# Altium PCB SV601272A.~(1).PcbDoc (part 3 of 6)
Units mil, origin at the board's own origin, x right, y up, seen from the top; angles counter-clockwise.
Board outline 8300 x 9520 mil, 8 copper layers (Top Layer, Signal Layer 1, Signal Layer 2, Signal Layer 3, Signal Layer 4, Signal Layer 5, Signal Layer 6, Bottom Layer), stack 59.2 mil thick; 551 components, 303 nets, 1611 pads, 1923 vias.
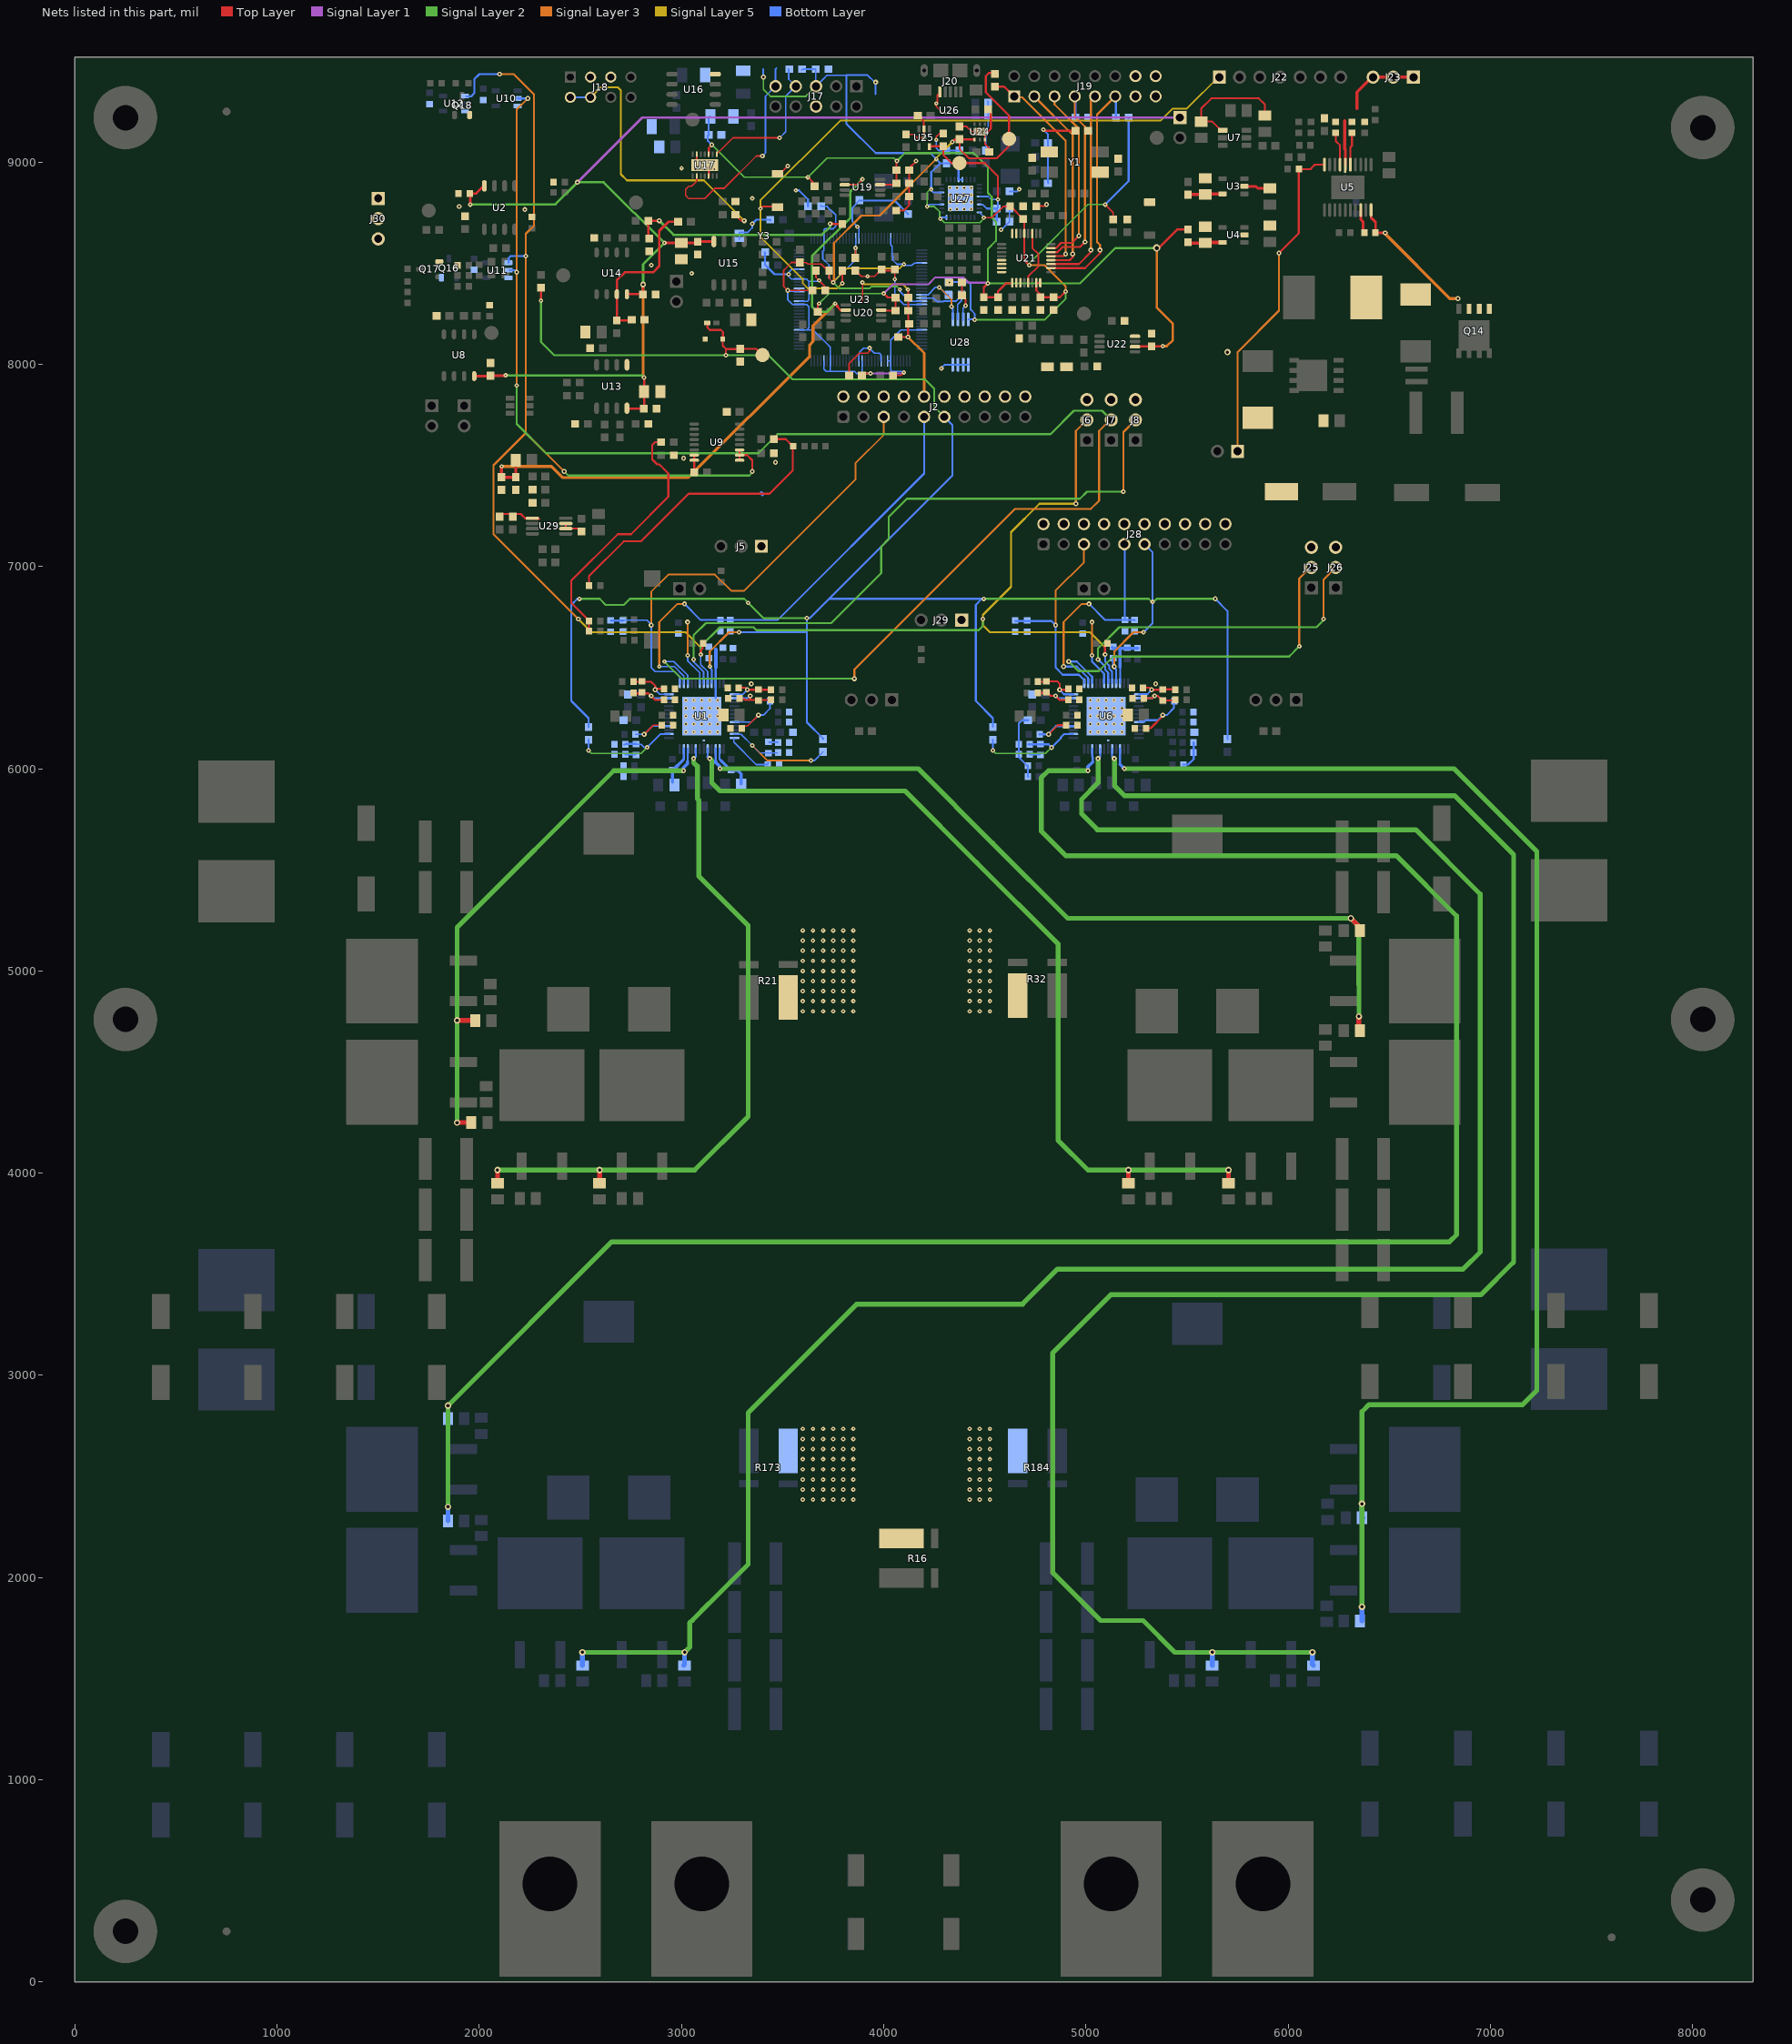
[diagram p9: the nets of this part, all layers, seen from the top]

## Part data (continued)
R142: "RES, 0, 5%, 0.1 W, 0603", Manufacturer=Vishay-Dale, Power_W=0.1, Supplier Part Number 1=541-0.0GCT-ND, TempCo="200 ppm/C", Tolerance_%=5, Value1=5%, Value2=0.1W, Value_Code=0000, ValueDisplayed=0
R143: "RES, 4.87 k, 1%, 0.1 W, 0603", Manufacturer=Vishay-Dale, Power_W=0.1, Supplier Part Number 1=541-4.87KHCT-ND, TempCo="100 ppm/C", Tolerance_%=1, Value1=1%, Value2=0.1W, Value_Code=4k87, ValueDisplayed=4.87k
R145: "RES, 2.00 k, 1%, 0.1 W, 0603", Manufacturer=Vishay-Dale, Power_W=0.1, Supplier Part Number 1=541-2.00KHCT-ND, TempCo="100 ppm/C", Tolerance_%=1, Value1=1%, Value2=0.1W, Value_Code=2k00, ValueDisplayed=2.00k
R146: "RES, 51, 5%, 0.1 W, 0603", Manufacturer=Vishay-Dale, Power_W=0.1, Supplier Part Number 1=541-51GCT-ND, TempCo="200 ppm/C", Tolerance_%=5, Value1=5%, Value2=0.1W, Value_Code=51R0, ValueDisplayed=51
R149: "RES, 1.00 k, 1%, 0.1 W, 0603", Manufacturer=Vishay-Dale, Power_W=0.1, Supplier Part Number 1=541-1.00KHCT-ND, TempCo="100 ppm/C", Tolerance_%=1, Value1=1%, Value2=0.1W, Value_Code=1k00, ValueDisplayed=1.00k
R153: "RES, 8.06 k, 1%, 0.1 W, 0603", Manufacturer=Vishay-Dale, Power_W=0.1, Supplier Part Number 1=541-8.06KHCT-ND, TempCo="100 ppm/C", Tolerance_%=1, Value1=1%, Value2=0.1W, Value_Code=8k06, ValueDisplayed=8.06k
R162: library part CMP-0025080-3, "RES, 2.00 k, 0.5%, 0.1 W, 0603", Manufacturer="Yageo America", Power_W=100mW, TempCo="50 ppm/C", Tolerance_%=0.5%, Value2=0.1W, Value_Code=2k00, ValueDisplayed=2.00k
R200: library part CMP-0023560-3, "RES, 4.87 k, 0.1%, 0.1 W, 0603", Manufacturer="Susumu Co Ltd", Power_W=100mW, Supplier Part Number 1=RG16P4.87KBCT-ND, TempCo="25 ppm/C", Tolerance_%=0.1%, Value2=0.1W, Value_Code=4k87, ValueDisplayed=4.87k
R201: "RES, 4.70, 0.5%, 0.1 W, 0603", Manufacturer="Yageo America", Power_W=0.1, TempCo="50 ppm/C", Tolerance_%=0.5, Value1=0.5%, Value2=0.1W, Value_Code=4R70, ValueDisplayed=4.70
S1: library part CMP-0002143-3, "Switch, Tactile, SPST-NO, 0.05A, 12V, SMT", CurrentRating_mA=50A, Manufacturer=E-Switch, PartNumber=TL1015AF160QG, Supplier Part Number 1=EG4344CT-ND
S2: "Switch, Tactile, SPST-NO, 0.05A, 12V, SMT", CurrentRating_mA=50, Manufacturer=E-Switch, Supplier Part Number 1=EG4344CT-ND
S3: "Switch"
T1 T2 T3 T4: "Terminal 70A Lug", Manufacturer=Panduit, Supplier Part Number 1=CXS70-14-C-ND
U1 U6: "Dual Channel 48V-12V Bidirectional Current Controller, PHP0048D", Alternate Manufacturer="Texas Instruments", Alternate PartNumber=LM5170QPHPTQ1
U2: library part LM6142AIM, "17MHz Rail-to-Rail Input and Output Op Amp, D0008A", Alternate Manufacturer="Texas Instruments"
U3 U4: "150-mA, 30-V, 1-uA IQ Voltage Regulators with Enable, DBV0005A", Alternate Manufacturer="Texas Instruments", Alternate PartNumber=TPS70950DBVT
U5: "Wide Voltage Range Buck-Boost Controller, 20-pin TSSOP-EP, Pb-Free", Manufacturer="Texas Instruments", PackageTopMarking=NSUZXYTT*LM5118*MH, PowerWise=Y, Supplier Part Number 1=LM5118MH-ND
U7: library part CMP-0072146-1, "Switched Capacitor Voltage Converter, 6-pin SOT-23", Manufacturer="Texas Instruments", PackageTopMarking=S03A*XTT, PowerWise=N
U8 U14: library part CMP-0041267-2, "Low-Noise, High-Precision, JFET-Input Operational Amplifier, 8 to 36 V, -40 to 125 degC, 8-pin SOIC (D8), Green (RoHS & no Sb/Br)", Manufacturer="Texas Instruments"
U9: library part CMP-0076549-1, "TRIPLE 2-CHANNEL ANALOG MULTIPLEXER/DEMULTIPLEXER, PW0016A (TSSOP-16)", Alternate Manufacturer="Texas Instruments"
U10: "Single Inverter Gate, DBV0005A", Alternate Manufacturer="Texas Instruments"
U11: "Single Power Supply 2-Input Positive NAND Gate CMOS Logic Level Shifter, DBV0005A", Alternate Manufacturer="Texas Instruments"
U12: "Single Power Supply 2-Input Positive OR Gate CMOS Logic Level Shifter, DBV0005A", Alternate Manufacturer="Texas Instruments"
U13: library part CMP-0079943-1, "50-uV Offset, 7-nV/vHz Noise, Low-Power, Precision Instrumentation Amplifier, D0008A (SOIC-8)", Alternate Manufacturer="Texas Instruments", Alternate PartNumber=INA828IDR
U15: library part CMP-0079847-1, "36-V Precision, Rail-to-Rail Output, Operational Amplifier, D0008A (SOIC-8)", Alternate Manufacturer="Texas Instruments"
U16: library part CMP-0032617-1, "Low Noise, Very Low Drift, Precision Voltage Reference, -40 to 125 degC, 8-pin SOIC (D), Green (RoHS & no Sb/Br)", Manufacturer="Texas Instruments", PartNumber=REF5050AID, Rating=Catalog, Temp Coeff(Max)(ppm/ degree C)=3
U17: library part CMP-0013342-2, "QUAD 16-BIT, 1LSB INL, BUFFERED, VOLTAGE-OUTPUT DIGITAL-to-ANALOG CONVERTERS, DMD0014A (VSON-14)", Alternate Manufacturer="Texas Instruments", PartNumber=DAC80004IDMD
U19 U20: library part CMP-0074888-1, "Low-Power, High Supply Range, 60-MHz, Fully Differential Amplifier, DGK0008A (VSSOP-8)", Alternate Manufacturer="Texas Instruments", Alternate PartNumber=THS4561IDGKT
U21: library part CMP-0075938-2, "24-Bit, 128kSPS, 4-Ch, Simultaneous Sampling, Delta-Sigma ADC, PBS0032A (TQFP-32)", Alternate Manufacturer="Texas Instruments", Alternate PartNumber=ADS131A04IPBS
U22: library part CMP-0032584-1, "Low Noise, Very Low Drift, Precision Voltage Reference, -40 to 125 degC, 8-pin MSOP(DGK), Green (RoHS & no Sb/Br)", Manufacturer="Texas Instruments", PartNumber=REF5025IDGKR, Rating=Military, Temp Coeff(Max)(ppm/ degree C)=3
U23: library part CMP-0029864-2, "Tiva C Series Microcontroller, 1024 KB Flash, 256 KB SRAM, 12 Bit, 20 Channels, -40 to 85 degC, 128-Pin TQFP (PDT), Green (RoHS & no Sb/Br), Tape and Reel", Manufacturer="Texas Instruments", Temperature Range="-40 to 85 degC"
U24: "1-A Low-Dropout Regulator With Reverse Current Protection, DRV0006A", Alternate Manufacturer="Texas Instruments", Alternate PartNumber=TPS73733DRVT
U25: "Single Output High PSRR LDO, 150 mA, Fixed 1.8 V Output, 2.5 to 6.5 V Input, with Low IQ, 5-pin SC70 (DCK), -40 to 85 degC, Green (RoHS & no Sb/Br)", Alternate Manufacturer="Texas Instruments", Alternate PartNumber=Equivalent, Supplier Part Number 1=296-19646-2-ND
U26: library part CMP-0043122-2, "USB ESD Solution with Power Clamp, 4 Channels, -40 to +85 degC, 6-pin SON (DRY), Green (RoHS & no Sb/Br)", Breakdown Voltage(Min)(V)=6, IO Capacitance(Typ)(pF)=0.8, IO Leakage Current(nA)=10, Manufacturer="Texas Instruments"
U27: "Highly Integrated Full Featured Hi-Speed USB 2.0 ULPI Transceiver, QFN-32", Manufacturer=Microchip, Supplier Part Number 1=USB3320C-EZK-ND
U28: "256K I2C™ CMOS Serial EEPROM, TSSOP-8", Manufacturer=Microchip, Supplier Part Number 1=24AA256-I/ST-ND
U29: "Low Noise Negative Bias Generator, 8-pin Mini SOIC, Pb-Free", Manufacturer="Texas Instruments", PackageTopMarking=ZXTT*F26A, PowerWise=N, Supplier Part Number 1=LM7705MM-ND
Y1: library part CMP-0004606-3, "Crystal, 16.384 MHz, 20 pF, SMD", Frequency_Fixed=16.384MHz, Frequency Stability=+/-50ppm, Manufacturer="CTS Electrocomponents", PartNumber=407F35E016M3840, Supplier Part Number 1=CTX682CT-ND
Y2: "Crystal, 25 MHz, 18 pF, SMD", Frequency="25 MHz", Frequency Stability=±30ppm, Manufacturer="Abracon Corportation", Supplier Part Number 1=535-10645-1-ND
Y3: "CRYSTAL, 32.768KHZ, 7PF, SMD", Frequency=32.768KHZ, Frequency Stability=±20ppm, Manufacturer="Seiko Instruments", Supplier Part Number 1=728-1065-1-ND
Y4: "Crystal, 24 MHz, 18 pF, SMD", Frequency="24 MHz", Frequency Stability=±30ppm, Manufacturer="Abracon Corportation", Supplier Part Number 1=535-10643-1-ND
ZZ1: library part AssemblyNoteLabel, Alternate Manufacturer=-
ZZ2 ZZ3 ZZ4: library part AssemblyNote, Alternate Manufacturer=-

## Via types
v1: diameter 32, hole 16, Top Layer to Bottom Layer, tented both sides, 622 vias
v2: diameter 24, hole 8, Top Layer to Bottom Layer, 380 vias
v3: diameter 22, hole 8, Top Layer to Bottom Layer, tented both sides, 346 vias
v4: diameter 32, hole 16, Top Layer to Bottom Layer, 237 vias
v5: diameter 24, hole 10, Top Layer to Bottom Layer, tented both sides, 153 vias
v6: diameter 19.68, hole 7.87, Top Layer to Bottom Layer, 70 vias
v7: diameter 24, hole 10, Top Layer to Bottom Layer, 47 vias
v8: diameter 28, hole 8, Top Layer to Bottom Layer, tented top, 24 vias
v9: diameter 22, hole 8, Top Layer to Bottom Layer, 19 vias
v10: diameter 19.68, hole 8, Top Layer to Bottom Layer, 16 vias
v11: diameter 50, hole 28, Top Layer to Bottom Layer, 4 vias
v12: diameter 36, hole 20, Top Layer to Bottom Layer, 2 vias
v13: diameter 26, hole 12, Top Layer to Bottom Layer, 1 vias
v14: diameter 28, hole 12, Top Layer to Bottom Layer, tented both sides, 1 vias
v15: diameter 24, hole 10, Top Layer to Bottom Layer, tented top, 1 vias

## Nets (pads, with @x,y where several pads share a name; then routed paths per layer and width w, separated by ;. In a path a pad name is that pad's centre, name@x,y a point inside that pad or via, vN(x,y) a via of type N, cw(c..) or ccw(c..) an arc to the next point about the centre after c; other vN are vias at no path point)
1.8V: C177.2 C178.2 C183.1 U25.5 U27.28 U27.30 V1.8.1 | length 842.3
  Top Layer w10: U25.5@4225,9080 4226.5,9078.5 C183.1@4295,9078.5 4295,9035 4335,8995 V1.8.1@4375,8995 4500,8995 4565,8930 v3(4565,8815)
  Bottom Layer w6: U27.30@4475,8790 4490,8790 4510,8770 4511.24,8770
  Bottom Layer w8: U27.28@4473.31,8829.84 4517.51,8829.84 4532.35,8815 v3@4560,8815 ; C177.2@4560,8770 4565,8775 v3(4565,8815)
  Bottom Layer w10: 4511.24,8770 C177.2@4558.5,8770 ; C178.2@4555,8705 4558.5,8708.5 C177.2@4558.5,8770 ; C177.2@4560,8770 C177.2@4558.5,8770
-0.2V: C228.1 C229.1 L8.1 U19.6 U20.6 | length 3366.9
  Top Layer w9: U19.6@3807.4,8887.8 3867.8,8887.8 v3(3895,8915)
  Top Layer w12: v3(3760,8300) 3771.95,8288.05 3771.95,8283.97 ; 3770,8285 3787.2,8267.8 U20.6@3812.4,8267.8 U20.6@3809.54,8270.65
  Top Layer w15: C229.1@2105,7445 2108.5,7441.5 C229.1@2110,7441.5 ; v3(2110,7495) C229.1@2110,7441.5 ; C228.1@2180,7441.5 C229.1@2110,7441.5 ; C228.1@2180,7445 L8.1@2180,7525
  Signal Layer 2 w12: v3(3760,8300) 3720,8260 3670,8260 3645,8285 3645,8535 3835,8725 3835,8855 v3(3895,8915)
  Signal Layer 3 w15: v3(2110,7495) 2356.29,7495 2411.29,7440 3035,7440 3633.63,8038.63 3633.63,8096.37 3650,8112.75 3650,8190 v3(3760,8300)
-5V: C97.1 C108.1 C109.1 C112.1 C119.1 C120.1 C189.1 J16.1 U2.4 U8.4 U13.4 U14.4 U15.4 | length 6559.2
  Top Layer w12: v3(1955,8790) 1955,8845 1985,8845 U2.4@2025,8885 ; U8.4@1975,7941.65 2053.35,7941.65 C97.1@2055,7940 ; C97.1@2055,7943.5 v9@2131.5,7943.5 ; U13.4@2730,7782.72 2732.72,7780 C108.1@2813.5,7780 2815,7780 v9(2815,7935) ; U14.4@2730,8346.65 2803.35,8346.65 C112.1@2805,8345 ; C112.1@2808.5,8345 v14@2808.5,8393.5 ; v9(2915,8600) C120.1@3000,8600 3080,8600 3087.28,8607.28 U15.4@3160,8607.28
  Signal Layer 1 w12: v5(2485,8900) 2805,9220 J16.1@5465,9220
  Signal Layer 2 w12: v3(1955,8790) 1955.87,8790.87 2375.87,8790.87 v5(2485,8900) 2615,8900 v9(2915,8600) 2810,8495 v14(2810,8395) ; v9(2130,7945) 2805,7945 v9(2815,7935)
  Signal Layer 3 w12: v14(2810,8395) 2810,7935 v9@2815,7930
ADC_SPI_CS: J19.5 U21.23 | length 902.8
  Top Layer w10: U21.23@4827.05,8574.21 4827.95,8575.12 4852.54,8575.12 4877.42,8600 4930,8600 v7(4965,8635)
  Signal Layer 3 w10: J19.5@4845,9325 4845,9285 4965,9165 v7(4965,8635)
ADC_SPI_DONE: J19.11 R123.1 U21.18 | length 1198.6
  Top Layer w10: U21.18@4827.05,8475.79 4995.79,8475.79 5070,8550 v7(5070,8565)
  Signal Layer 3 w10: v7(5070,8565) 5070,8590 5055,8605 5055,9235 J19.11@5145,9325
  Bottom Layer w10: J19.11@5145,9325 5148.5,9321.5 R123.1@5148.5,9220
ADC_SPI_DRDY: J19.9 U21.19 | length 1000.9
  Top Layer w10: U21.19@4827.05,8495.47 4965.47,8495.47 5025,8555 v7(5025,8565)
  Signal Layer 3 w10: v7(5025,8565) 5025,8585 5025,9305 J19.9@5045,9325
ADC_SPI_MISO: J19.1 R122.1 U21.21 | length 1098.4
  Top Layer w10: R122.1@4550,9373.5 4596.5,9373.5 J19.1@4645,9325 J19.1@4646.5,9323.5 ; U21.21@4827.05,8534.84 4889.84,8534.84 v7(4900,8545)
  Signal Layer 3 w10: J19.1@4645,9320 4685,9320 4900,9105 v7(4900,8545)
ADC_SPI_MOSI: J19.3 U21.20 | length 987.8
  Top Layer w10: U21.20@4827.05,8515.16 4920.16,8515.16 4935,8530 v7(4935,8545)
  Signal Layer 3 w10: J19.3@4745,9325 4935,9135 v7(4935,8545)
ADC_SPI_SCLK: J19.7 R138.2 U21.22 | length 1043.1
  Top Layer w10: U21.22@4827.05,8554.53 4859.53,8554.53 4885,8580 4970,8580 v7(4995,8605)
  Signal Layer 3 w10: J19.7@4945,9330 J19.7@4945,9325 4945,9225 4995,9175 v7(4995,8605)
  Bottom Layer w10: J19.7@4940,9325 4948.5,9316.5 R138.2@4948.5,9220
AGND: C1.2 C2.1 C3.1 C5.2 C6.2 C8.2 C9.1 C11.2 C13.2 C14.2 C16.2 C17.2 C19.1 C31.2 C33.2 C34.2 C35.2 C36.2 C37.2 C44.2 C45.2 C72.2 C73.2 C74.2 C75.2 C76.2 C78.2 C82.2 C83.2 C84.2 C90.2 C91.1 C93.2 C94.1 C96.2 C97.2 C98.2 C99.1 C100.2 C104.2 C105.2 C106.2 C107.2 C108.2 C109.2 C110.2 C111.2 C112.2 C113.1 C116.2 C117.2 C118.1 C119.2 C120.2 C121.1 C122.2 C123.2 C124.2 C125.2 C126.2 C127.2 C128.2 C131.2 C132.2 C133.2 C134.2 C135.2 C136.2 C137.2 C138.2 C139.2 C140.2 C141.2 C145.1 C146.1 C149.1 C152.2 C153.2 C155.2 C156.2 C157.2 C158.2 C159.2 C160.2 C161.2 C189.2 C190.2 C191.2 C194.2 C196.2 C197.2 C199.2 C200.2 C202.2 C203.2 C204.2 C205.2 C218.2 C223.2 C224.2 C225.2 C226.2 C227.2 C228.2 C229.2 D5.2 J2.2 J2.4 J2.6 J2.8 J2.10 J2.12 J2.14 J2.16 J2.18 J2.20 J5.1 J6.3 J7.3 J8.3 J17.6 J18.3 J18.5 J19.13 J19.14 J19.15 J19.16 J23.1 J23.2 J23.3 J25.3 J26.3 J28.2 J28.4 J28.6 J28.8 J28.10 J28.12 J28.14 J28.16 J28.18 J28.20 J29.1 J30.1 J30.2 J30.3 NT1.1 NT2.1 NT3.1 Q16.2 Q17.2 Q18.2 R2.2 R3.2 R6.1 R7.2 R9.2 R11.1 R13.1 R15.1 R17.1 R18.1 R19.1 R20.1 R23.2 R46.1 R49.1 R67.1 R78.1 R86.2 R87.1 R89.2 R92.1 R112.1 R126.1 R138.1 R147.2 R148.1 R156.1 R158.1 R167.1 R169.1 R170.1 R171.1 R172.1 S1.2 U1.42 U1.46 U1.49 U3.2 U4.2 U5.6 U6.42 U6.46 U6.49 U7.1 U9.7 U9.8 U10.3 U11.3 U12.3 U13.5 U16.4 U17.6 U17.12 U17.15 U21.5 U21.6 U21.7 U21.8 U21.10 U21.11 U21.13 U21.27 U21.31 U21.32 U22.4 U29.2 U29.3 U29.5 Y1.2 Y1.4 | length 5161.6
  Top Layer w8: 3895,8315 v3(3895,8405)
  Top Layer w9: R112.1@4061.5,8760 4100,8760 4125,8785 C134.2@4125,8960 ; C132.2@4120,8190 C132.2@4130,8200 ; v3(4120,8370) 4121.5,8368.5 C136.2@4121.5,8330 C135.2@4121.5,8265 ; C132.2@4121.5,8208.5 C132.2@4125,8205 ; C134.2@4126.5,8960 4126.5,8971.5 v5(4160,9005) ; U21.13@4715,8405 4715,8435 4765,8485 4765,8545 4734.53,8575.47 U21.27@4734.53,8647.05 ; U21.27@4733.12,8648.12 U21.27@4735,8650 ; C156.2@4755,8781.5 4796.5,8781.5 v5(4805,8790) ; U7.1@5676.93,9157.4 5667.6,9157.4 5625,9200 C78.2@5570,9200 5570,9265 5620,9315 5855,9315 5885,9285 C76.2@5885,9230
  Top Layer w9.8: C225.2@2095,7260 2205,7260 2226.61,7238.39 U29.5@2262.32,7238.39 2266.28,7234.43 2295.89,7234.43 ; U29.2@2427.68,7187.2 2487.8,7187.2 C223.2@2510,7165 ; U29.2@2427.68,7187.68 U29.3@2427.68,7212.8 ; U9.7@3062.8,7551.02 U9.8@3062.8,7525.43 3062.8,7462.2 R67.1@3065,7460
  Top Layer w10: U17.15@3065,9005 3075.63,9015.63 U17.6@3075.63,9039.13 ; U17.12@3134.69,8930.87 3134.69,8964.68 U17.15@3135,8965 ; R126.1@4071.5,8135 v5(4120,8135) C132.2@4120,8190 ; C132.2@4121.5,8208.5 C135.2@4121.5,8265
  Top Layer w13: U3.2@5777.24,8880 U3.2@5784.13,8880 5840,8880 5850,8870 C34.2@5910,8870 ; 6280,9065 6282.2,9062.8 U5.6@6282.2,8987.2
  Top Layer w15: 6340,9265 6340,9345 6415,9420 J23.3@6420,9420 J23.2@6520,9420 J23.1@6620,9420
  Top Layer w16: v6(3178.74,6260) C6.2@3214.57,6260 ; 6280,9065 6280,9205
  Signal Layer 3 w10: v3(3030,6560) v5(3030,6725) ; v5(5030,6560) v5(5030,6725)
  Signal Layer 3 w12: v5(4120,8135) 4200,8055 J2.10@4200,7840 J2.10@4200,7820
  Signal Layer 5 w9: v3(3895,8405) 3903.37,8396.63 4093.37,8396.63 v3(4120,8370)
  Bottom Layer w8: v3@3030,6557.7 3030,6535 3090.16,6474.84 U1.42@3090.16,6418.46
  Bottom Layer w9: U6.46@5168.9,6422.4 5168.9,6503.9
  Bottom Layer w9.8: U1.49@3168.9,6348.58 3168.9,6418.46 3168.9,6500 ; R170.1@4710,6015 4667.44,6057.56 C19.1@4667.44,6120 4667.44,6222.44 4685,6240 R167.1@4713.5,6240 R167.1@4715,6240 ; R170.1@4712.44,6015 4712.44,5962.56 C203.2@4715,5960 ; v5(5030,6560) 5030,6530 5079.68,6480.32 5079.68,6480.01 5090.16,6469.53 U6.42@5090.16,6422.4 ; C197.2@5480,6020 C197.2@5482.56,6020 5505.12,6020 5532.56,6047.44 R172.1@5532.56,6130
  Bottom Layer w16: 3170,6500 3170,6508.9 ; 3170,6512.8 3170,6590 ; 3395,7365 3400,7360 3400,7355 ; C196.2@5130,6600 5134.11,6595.89 5168.9,6595.89 ; 5168.9,6503.9 5168.9,6595.89 ; 5168.9,6598.9 5168.9,6595.89 ; R148.1@5255,6595.89 5168.9,6595.89
  other v1: 5700,8060
  other v5: 3345,6420 5345,6420 3465,7515 3010,7535 2225,8765 1900,8780
  other v6: 3021.26,6181.26 3060.63,6181.26 3100,6181.26 3139.37,6181.26 3178.74,6181.26 5021.26,6181.26 5060.63,6181.26 5100,6181.26 5139.37,6181.26 5178.74,6181.26 3021.26,6220.63 3060.63,6220.63 3100,6220.63 3139.37,6220.63 3178.74,6220.63 5021.26,6220.63 5060.63,6220.63 5100,6220.63 5139.37,6220.63 5178.74,6220.63 3021.26,6260 3060.63,6260 3100,6260 3139.37,6260 5021.26,6260 5060.63,6260 5100,6260 5139.37,6260 5178.74,6260 3021.26,6299.37 3060.63,6299.37 3100,6299.37 3139.37,6299.37 3178.74,6299.37 5021.26,6299.37 5060.63,6299.37 5100,6299.37 5139.37,6299.37 5178.74,6299.37 3021.26,6338.74 3060.63,6338.74 3100,6338.74 3139.37,6338.74 3178.74,6338.74 5021.26,6338.74 5060.63,6338.74 5100,6338.74 5139.37,6338.74 5178.74,6338.74 3067.76,8965.32 3115,8965.32 3162.24,8965.32 3067.76,9004.68 3115,9004.68 3162.24,9004.68
  other v9: 3050,8450 2850,8490 3350,8820 3000,8970
AVDD: C126.1 C127.1 C133.1 C134.1 C135.1 C136.1 C137.1 C138.1 C160.1 R116.2 R131.2 R165.2 U17.3 U19.3 U20.3 U21.9 U22.2 | length 5792.8
  Top Layer w10: U17.3@3134.69,9039.13 3134.69,9069.68 v7(3150,9085) ; v3(3625,8925) 3658.5,8891.5 R116.2@3658.5,8880 ; R131.2@3673.5,8260 3673.5,8293.5 v3(3680,8300) ; U19.3@3982.6,8887.8 4057.8,8887.8 C133.1@4065,8895 ; U20.3@3985,8265 C135.1@4058.5,8265 ; v3(4000,8350) 4020,8330 C136.1@4058.5,8330 4058.5,8266.5 C135.1@4060,8265 ; v3@4063.5,9003.5 C134.1@4063.5,8960 4063.5,8901.5 C133.1@4065,8900 ; C138.1@4495,8330 4496.5,8331.5 C137.1@4565,8331.5 4565,8360 4605,8400 U21.9@4635,8400 ; C138.1@4495,8331.5 4495,8380 v9(4515,8400) ; U22.2@5240,8090 5241.5,8088.5 C160.1@5325,8088.5 5378.5,8088.5 v3(5380,8090)
  Top Layer w12: v12(5350,8575) 5360,8575 5451.5,8666.5 R165.2@5505,8666.5
  Signal Layer 1 w10: v3(4000,8350) 4046.13,8396.13 4221.13,8396.13 4255,8430 4395,8430 4420,8405 ; 4420,8403.87 4511.13,8403.87 v9(4515,8400)
  Signal Layer 2 w8: v7(3150,9085) 3310,8925 v3(3625,8925) 3720,9020 4050,9020 v3(4065,9005) ; v3@3675,8300 v3(3680,8300) 3730,8350 v3(4000,8350)
  Signal Layer 2 w10: v3(4065,9005) 4105,9045 4445,9045 4515,8975 4515,8847.75 4533.87,8828.87 4533.87,8725 ; 4535,8725 4555,8705 4555,8610 4515,8570 v9(4515,8400) 4970,8400 5145,8575 v12(5350,8575)
  Signal Layer 3 w12: v12(5350,8575) 5350,8280 5430,8200 5430,8120 5400,8090 v3(5380,8090)
  Bottom Layer w10: C127.1@3133.5,9135 3133.5,9218.5 C126.1@3140,9225 ; C127.1@3135,9135 3130,9130 3130,9105 v7(3150,9085)
CLRn: J17.9 U17.9 | length 1064.9
  Top Layer w8: U17.9@3075.63,8930.87 3075.63,8905.63 3050,8880 3035,8880 3020,8865 3020,8835 3035,8820 3115,8820 3165,8870 3210,8870 3370,9030 v7(3400,9030)
  Bottom Layer w8: v7(3400,9030) 3415,9045 3415,9325 J17.9@3465,9375 3465,9460 3470,9465
CS1A: C72.1 C80.1 R56.1 U1.36 | length 267.6
  Top Layer w9.8: R56.1@2753.62,6420 R56.1@2758.62,6420 ; R56.1@2762.56,6430 2850,6430 2870,6410 v5(2870,6390) ; v5@2875,6395 C72.1@2912.44,6395 C72.1@2921.38,6395
  Bottom Layer w8: v5(2870,6390) 2891.73,6368.27 U1.36@2941.54,6368.27
CS1B: C73.1 C80.2 R57.1 U1.35 | length 268.7
  Top Layer w9.8: R57.1@2762.33,6372.33 2837.67,6372.33 v5(2850,6360) 2870,6340 C73.1@2921.38,6340
  Bottom Layer w8: v5(2850,6360) 2861.42,6348.58 U1.35@2941.54,6348.58
CS2A: C75.1 C81.2 R58.1 U1.1 | length 246.1
  Top Layer w9.8: C75.1@3278.62,6400 C75.1@3282.56,6400 3315,6400 v5(3325,6390) R58.1@3442.44,6390 R58.1@3445,6390
  Bottom Layer w8: U1.1@3258.46,6368.27 3303.27,6368.27 v5(3325,6390)
CS2B: C74.1 C81.1 R59.1 U1.2 | length 271.6
  Top Layer w9.8: C74.1@3285,6345 3310,6345 3315,6340 3340,6340 ; v5(3340,6360) 3340,6340 ; R59.1@3440,6340 3340,6340
  Signal Layer 3 w9.8: v5(3340,6360) v5@3345.31,6360
  Bottom Layer w8: U1.2@3258.46,6348.58 3328.58,6348.58 3335,6355 v5@3345,6355
CS3A: C95.1 C190.1 R177.1 U6.36 | length 264.2
  Top Layer w9.8: R177.1@4762.56,6430 C95.1@4805,6430 ; C95.1@4805,6432.56 4857.44,6432.56 4870,6420 v5(4870,6390) C190.1@4915,6390
  Bottom Layer w9.8: v5(4870,6390) 4891.73,6368.27 U6.36@4937.6,6368.27
CS3B: C95.2 C191.1 R178.1 U6.35 | length 268.4
  Top Layer w10: R178.1@4762.56,6375 C95.2@4805,6375 ; C95.2@4805,6380 4825,6360 v5(4850,6360) 4870,6340 C191.1@4912.44,6340 C191.1@4915,6340
  Bottom Layer w9.8: v5@4845,6365 v5(4850,6360) 4861.42,6348.58 U6.35@4937.6,6348.58
CS4A: C198.2 C200.1 R186.1 U6.1 | length 238.9
  Top Layer w10: C200.1@5280,6395 5285,6400 5315,6400 v5(5325,6390) C198.2@5380,6390 ; C198.2@5380,6392.56 5437.44,6392.56 R186.1@5440,6390
  Bottom Layer w10: U6.1@5262.4,6368.27 5303.27,6368.27 v5(5325,6390)
CS4B: C198.1 C199.1 R187.1 U6.2 | length 257.4
  Top Layer w10: C199.1@5286.02,6348.58 5328.58,6348.58 v5(5340,6360) 5355,6360 C198.1@5380,6335 ; C198.1@5380,6337.44 5442.44,6337.44 R187.1@5445,6340
  Bottom Layer w10: U6.2@5262.4,6348.58 5328.58,6348.58 v5(5340,6360)
DGND: C162.2 C163.1 C164.2 C165.1 C166.1 C167.1 C168.1 C169.1 C170.1 C171.1 C172.2 C173.2 C174.1 C175.2 C176.1 C177.1 C178.1 C179.2 C180.2 C181.2 C182.2 C183.2 C184.2 C185.1 C186.1 C187.1 C188.2 J20.5 R143.2 R147.1 R153.1 R154.1 S2.1 U23.10 U23.17 U23.48 U23.55 U23.58 U23.80 U23.114 U24.3 U24.7@4475,9150 U25.2 U26.4 U27.33 U28.1 U28.2 U28.3 U28.4 U28.7 Y3.2 Y3.3 | length 4664.5
  Top Layer w6: C179.2@4515,9255 4530,9240
  Top Layer w8: S2.1@3475,8942.68 3487.68,8942.68 v3(3525,8980) ; C169.1@3665,8460 3665,8430 v3(3680,8415) 3711.5,8383.5 C168.1@3711.5,8365 ; C165.1@3828.5,7945 3828.5,8003.5 3880,8055 3920,8055 3930,8065 v3(3930,8080) ; C167.1@3860,8463.5 3888.5,8435 v3(3920,8435) 3955,8435 C172.2@3983.5,8463.5 ; C172.2@3990,8470 C172.2@3983.5,8463.5 ; v3(4055,8420) C173.2@4055,8465 ; C173.2@4055,8468.5 C173.2@4055,8465 ; C184.2@4110,9136.5 4148.5,9136.5 4165,9120 v3(4200,9120) U25.2@4200,9164.29 4200,9165 4198.5,9166.5 4198.5,9200 C182.2@4168.5,9230 ; v3(4260,9110) 4260,9125 4276.5,9141.5 C183.2@4295,9141.5 ; J20.5@4280,9345 4265,9330 4265,9295 v3(4260,9290) 4260,9275 4290,9245 U26.4@4305,9245 ; C166.1@4375,8420 4375,8405 C166.1@4386.5,8405 C174.1@4386.5,8343.5 ; C180.2@4375,9176.5 4408.5,9176.5 4435,9150 U24.7@4450,9150 ; C174.1@4385,8345 C174.1@4386.5,8343.5 ; v3(4405,8290) 4405,8325 C174.1@4386.5,8343.5 ; U24.3@4500,9115 4500,9090 4521.5,9068.5 C181.2@4521.5,9050 ; U24.3@4500.59,9111.61 U24.7@4500.59,9144.41 ; C172.2@3983.5,8463.5 4053.5,8463.5 C173.2@4055,8465
  Top Layer w10: U24.7@4495,9150 v6(4496.65,9150) 4515,9150 4530,9165 4530,9240 4530,9246.5 C179.2@4516.5,9260 ; v3(4790,9160) 4795,9155 R147.1@4948.5,9155
  Bottom Layer w6: v9@3530,8455 3544.61,8469.61 U23.58@3581.85,8469.61 ; 3540,8425 3542.64,8422.36 U23.55@3581.85,8422.36 3617.64,8422.36 3620,8420 ; U23.48@3581.85,8312.13 3622.13,8312.13 3630,8320 3630,8335 ; v3(3870,8680) 3877.13,8672.87 U23.80@3877.13,8623.15 ; U23.17@3877.13,8016.85 3878.06,8017.79 3878.06,8051.22 3882.13,8055.28 3882.13,8062.13 3900,8080 v3(3930,8080) 3954.72,8055.28 3978.78,8055.28 3986.43,8047.64 3986.43,8017.79 U23.10@3987.36,8016.85 ; 4095,8300 4098.62,8296.38 U23.114@4188.15,8296.38
  Bottom Layer w8: Y3.2@3285.98,8617.28 Y3.3@3285.98,8652.72 3327.72,8652.72 3350,8675 v3(3350,8695) ; C170.1@3410,8555 3413.5,8551.5 R143.2@3413.5,8490 ; v9@3530,8455 v9(3530,8445) 3530,8435 3540,8425 ; 3620,8420 3630,8410 ; 3630,8335 3630,8410 ; v3(3680,8415) 3675,8410 3630,8410 ; v3(3870,8680) 3845,8705 3845,8775 C162.2@3880,8810 ; v3(4055,8420) 4055,8340 4095,8300 ; v3(4260,9110) 4260,9070 4273.5,9056.5 C176.1@4310,9056.5 4373.5,9056.5 C175.2@4375,9055 ; v3(4285,7980) 4302.8,7997.8 U28.4@4341.61,7997.8 U28.3@4367.2,7997.8 U28.2@4392.8,7997.8 4417.8,7997.8 U28.1@4420,8000 ; U28.7@4390.3,8219.7 U28.7@4392.8,8217.2 ; U28.7@4392.8,8222.2 4392.8,8277.8 v3(4405,8290) ; v6@4495.83,9149.17 4505,9140 R153.1@4505,9056.5 ; v6@4495.83,9150.83 4516.5,9171.5 C187.1@4516.5,9230 4516.5,9298.5 C188.2@4515,9300 ; v3@4581.5,8665 C178.1@4621.5,8705 C177.1@4621.5,8770 ; R154.1@4621.5,8855 4660,8855 v3(4670,8865) ; v3(4790,9160) 4811.5,9138.5 C186.1@4811.5,9095 4811.5,8898.5 C185.1@4815,8895
  Bottom Layer w10: v3(3350,8695) 3370,8715 C171.1@3438.5,8715 ; R143.2@3415,8490 3460,8445 v9(3530,8445) ; C171.1@3438.5,8710 3438.5,8713.5 C171.1@3440,8715 ; v3(3565,8860) 3580,8860 3625,8815 C163.1@3625,8781.5 ; C162.2@3880,8810 4053.5,8810 C164.2@4120,8743.5
  other v3: 4580,8665
  other v6: 4453.35,9150
  other v10: 4330,8765 4362.28,8766.85 4397.72,8766.85 4433.15,8766.85 4326.85,8802.28 4362.28,8802.28 4397.72,8802.28 4433.15,8802.28 4326.85,8837.72 4362.28,8837.72 4397.72,8837.72 4433.15,8837.72 4326.85,8873.15 4362.28,8873.15 4397.72,8873.15 4433.15,8873.15
DIR: J6.2 R102.2 R144.2 U1.44 U6.44 U9.9 U9.10 U9.11 U11.1 U12.1 | length 9504.4
  Top Layer w10: v3(3095,6565) 3095,6585 3105,6595 R102.2@3105,6620 ; U9.11@3287.2,7576.61 3287.2,7552.8 U9.10@3288.98,7551.02 ; U9.9@3290,7525 3287.2,7527.8 U9.10@3287.2,7551.02 U9.10@3288.98,7551.02 ; v5(3350,7470) 3350,7525 3323.98,7551.02 U9.10@3288.98,7551.02
  Top Layer w12: v5(5095,6565) 5095,6610 R144.2@5105,6620
  Signal Layer 2 w10: v5(2420,7470) 2440,7450 3335,7450 v5@3350,7465 ; v3(3095,6565) 3095,6605 3190,6700 3355,6700 3370,6685 4470,6685 4490,6705 v3(4490,6740)
  Signal Layer 3 w10: v5(2100,9435) 2170,9435 2270,9335 2270,8685 2230,8645 v5(2230,8535) 2230,7660 ; v5(2420,7470) 2230,7660 ; v7(2490,6740) 2070,7160 2070,7500 2230,7660 ; v5(4950,7310) 4950,7670 J6.2@5005,7725
  Signal Layer 5 w10: v7(2490,6740) 2555,6675 3020,6675 3095,6600 v3(3095,6565) ; v5(4950,7310) 4770,7310 4630,7170 4630,6900 4490,6760 v3(4490,6740) 4490,6710 4525,6675 5020,6675 5095,6600 v5(5095,6565)
  Bottom Layer w8: v3(3095,6565) 3095,6514.9 3129.53,6480.37 U1.44@3129.53,6418.46
  Bottom Layer w10: U12.1@1935,9325 1960,9325 1975,9340 1975,9410 2000,9435 v5(2100,9435) ; U11.1@2144.13,8502.4 2145,8503.27 2145,8525 2155,8535 v5(2230,8535) v5@2235,8535 ; v5(5095,6565) 5095,6530.14 5112.77,6512.36 5112.77,6512.23 5115.13,6509.87 5115.13,6494.7 5129.53,6480.3 U6.44@5129.53,6422.4
DVDD_3.3V: C128.1 C139.1 C140.1 C141.1 C165.2 C166.2 C167.2 C168.2 C175.1 C176.2 C180.1 DVDD_3V3.1 J17.5 R99.1 R120.2 R121.2 R122.2 R123.2 R139.2 R140.2 R142.1 R146.1 R151.2 R152.2 U21.15 U21.16 U21.29 U23.7 U23.8 U23.16 U23.26 U23.28 U23.39 U23.47 U23.51 U23.52 U23.69 U23.79 U23.90 U23.101 U23.113 U23.122 U24.1 U27.8 U27.11 U27.14 U27.20 U27.21 U27.32 U28.8 | length 11723.3
  Top Layer w6: R140.2@3585,8503.5 3616.5,8503.5 3625,8495 3690,8495
  Top Layer w8: R140.2@3585,8503.5 3543.5,8503.5 3505,8465 3505,8385 v7(3525,8365) C168.2@3648.5,8365 ; 3690,8495 3721.5,8463.5 R139.2@3730,8463.5 3730,8425 v3(3750,8405) ; C167.2@3860,8526.5 v3(3860,8575) ; C165.2@3890,7945 3900,7955 v3(3935,7955) ; v7@3955,9400 v7@3960,9400 ; R142.1@4046.5,7945 4085,7945 v3(4100,7960) ; v3(4495,8725) 4535,8725 4590,8780 R120.2@4625,8780 ; v3(5095,8790) 5135,8750 R121.2@5135,8716.5
  Top Layer w10: v3(4340,9100) 4353.5,9113.5 C180.1@4375,9113.5 C180.1@4375,9110 ; U24.1@4449.41,9111.61 4376.61,9111.61 C180.1@4375,9110 ; R122.2@4545,9440 4520,9440 4505,9425 4505,9345 4620,9230 DVDD_3V3.1@4620,9115 ; R120.2@4625,8780 4628.5,8780 C141.1@4690,8718.5 ; DVDD_3V3.1@4625,9115 4625,9085 4558.43,9018.43 4421.57,9018.43 4375,9065 C180.1@4375,9110 ; C141.1@4690,8720 4695.16,8714.84 U21.29@4695.16,8647.05 4695.16,8514.84 v3(4720,8490) ; U21.16@4773.9,8402.95 4757.05,8402.95 4755,8405 4755,8365 4775,8345 C139.1@4775,8331.5 4838.5,8331.5 C140.1@4840,8330 ; C140.1@4840,8331.5 4871.5,8331.5 v3(4900,8360)
  Signal Layer 1 w8: v3(3935,7955) 4095,7955 v3(4100,7960)
  Signal Layer 2 w8: v5(3405,9420) 3405,9360 3440,9325 3615,9325 J17.5@3665,9375 ; v3(3750,8405) 3780,8375 3930,8375 3940,8385 4065,8385 v3(4080,8370) ; v3(4235,8865) 4230,8865 4215,8850 v3(4215,8780) 4250,8780 4276.87,8753.13 4276.87,8723.13 v3(4280,8720) 4300,8700 4475,8700 4495,8720 v3(4495,8725) ; v3(4450,8220) 4795,8220 4900,8325 v3(4900,8360) ; v3(4720,8490) 4720,8500 5010,8790 v3(5095,8790)
  Signal Layer 3 w10: v3(3750,8405) 3753.87,8408.87 3753.87,8598.87 3890,8735 3980,8735 v3(4260,9015) ; v3(4720,8490) 4795,8490 4900,8385 v3(4900,8360)
  Signal Layer 5 w8: v3(3750,8405) 3820,8475 4080,8475 v3(4100,8495)
  Signal Layer 5 w10: v3(4260,9015) 4260,9020 v3(4340,9100)
  Bottom Layer w6: 3540,8305 3548.62,8296.38 U23.47@3581.85,8296.38 3618.62,8296.38 3630,8285 3630,8275 ; U23.39@3581.85,8170.39 3620.39,8170.39 ; 3630,8180 3620.39,8170.39 ; 3635,8170 3634.61,8170.39 3620.39,8170.39 ; U23.28@3703.9,8016.85 3703.9,7976.1 3715,7965 ; 3705,8565 3703.9,8566.1 U23.69@3703.9,8623.15 3703.9,8663.9 3705,8665 ; 3730,8090 3735.39,8084.61 U23.26@3735.39,8016.85 3735.39,7965.39 3735,7965 ; v3(3860,8575) 3861.38,8576.38 U23.79@3861.38,8623.15 ; 3890,7955 3892.87,7957.87 U23.16@3892.87,8016.85 ; U23.8@4018.86,8016.85 4033.15,8016.85 U23.7@4034.61,8015.39 ; U23.90@4034.61,8623.15 4034.61,8591.33 4041.87,8584.06 4041.87,8538.13 ; 4040,7965 4034.61,7970.39 U23.7@4034.61,8015.39 ; v3(4080,8370) 4080,8360 4127.87,8312.13 U23.113@4188.15,8312.13 ; v3(4100,8495) 4106.87,8488.13 4139.06,8488.13 4152.04,8501.1 U23.101@4188.15,8501.1 ; U23.122@4188.15,8170.39 4085.39,8170.39 4035,8120 4035,8015 U23.7@4034.61,8015.39
  Bottom Layer w8: v5@3403.5,9421.5 3403.5,9460 ; 3540,8305 3525,8320 v7(3525,8365) 3528.15,8361.85 3581.85,8361.85 3581.85,8370 ; R99.1@3595,9455 R99.1@3596.36,9456.36 ; R99.1@3596.31,9454.95 R99.1@3596.36,9456.36 ; 3630,8180 3630,8275 ; 3635,8170 3650,8170 3730,8090 ; J17.5@3663.5,9378.5 C128.1@3663.5,9460 3600,9460 R99.1@3596.36,9456.36 ; J17.5@3665,9375 3708.39,9418.39 ; R146.1@3690,8781.5 R146.1@3693.5,8781.5 ; R146.1@3690,8785 R146.1@3693.5,8781.5 ; 3703.9,8563.9 3698.13,8558.13 3698.13,8521.87 3730,8490 3730,8425 v3(3750,8405) 3860,8515 v3(3860,8575) ; 3705,8665 3710,8670 3750,8670 3762.87,8682.87 3762.87,8737.87 3720.75,8780 3720,8780 3718.5,8781.5 R146.1@3693.5,8781.5 ; 3710,9420 3719.43,9429.43 3814.43,9429.43 3815,9430 3920,9430 3955,9395 v7(3960,9395) 3960,9335 ; 3715,7965 3735,7965 3855,7965 3865,7955 3890,7955 v3(3935,7955) ; 4040,7965 4095,7965 v3(4100,7960) ; 4041.87,8536.87 4045,8533.75 4045,8515 4065,8495 v3(4100,8495) ; v3(4215,8780) 4225.47,8790.47 U27.11@4286.69,8790.47 ; v3(4235,8865) 4230,8865 4245.47,8849.53 U27.14@4286.69,8849.53 ; v3(4280,8720) 4286.69,8726.69 U27.8@4311.1,8726.69 ; R151.2@4326.5,8406.5 R152.2@4385,8406.5 ; R152.2@4385,8405 4420,8405 4430,8395 4430,8270 4450,8250 v3(4450,8220) 4447.8,8222.2 U28.8@4418.39,8222.2 ; U27.32@4473.31,8751.1 4499.41,8725 v3(4495,8725)
  Bottom Layer w10: 3815,9430 3815,9190 3960,9045 4230,9045 v3(4260,9015) 4281.5,8993.5 ; v3(4235,8865) 4235,8950 4278.5,8993.5 4281.5,8993.5 ; C176.2@4310,8993.5 4281.5,8993.5 ; C176.2@4311.5,8993.5 C175.1@4373.5,8993.5 ; U27.20@4370,8915 U27.20@4370.16,8914.84 ; C175.1@4375,8993.5 C175.1@4373.5,8993.5 ; U27.21@4389.84,8913.31 4371.69,8913.31 U27.20@4370.16,8914.84 ; v3(5095,8790) 5211.5,8906.5 R123.2@5211.5,9220 ; U27.20@4370.16,8914.84 4370.16,8990.16 C175.1@4373.5,8993.5
  other v9: 4325,8405
EN: J7.2 U1.39 U10.2 U11.2 | length 8029.2
  Signal Layer 2 w10: v3(2185,7895) 2185,7705 2330,7560 3090,7560 3380,7560 3475,7655 4825,7655 4940.35,7770.35 5079.65,7770.35 J7.2@5125,7725 ; v3(2915,6530) 3000,6445 v5(3855,6445)
  Signal Layer 3 w10: v3(2185,7895) v5(2185,8455) 2185,9260 v5(2240,9315) ; v5(3855,6445) 3855,6490 4650,7285 5025,7285 5065,7325 ; 5065,7335 5065,7325 ; J7.2@5125,7725 5120,7725 5065,7670 5065,7325
  Bottom Layer w8: v3(2915,6530) 2962.55,6530 3031.1,6461.45 U1.39@3031.1,6418.46
  Bottom Layer w10: U11.2@2150,8465 2175,8465 v5(2185,8455) ; U10.2@2190,9315 v5(2240,9315)
EN2: J8.2 U1.43 | length 3201.7
  Signal Layer 2 w10: v3(3060,6540) 3060,6660 3120,6720 3740,6720 3987.13,6967.13 3987.13,7097.87 4025,7135.75 4025,7245 4115,7335 4970,7335 5005,7370 v5(5185,7370)
  Signal Layer 3 w10: v5(5185,7370) 5185,7665 J8.2@5245,7725
  Bottom Layer w8: v3(3060,6540) 3060,6527.45 3109.84,6477.61 U1.43@3109.84,6418.46
EN3: J25.2 U6.39 | length 1809.4
  Signal Layer 2 w10: v5(4915,6530) 4962.5,6482.5 5062.5,6482.5 5135,6555 6005,6555 ; 6010,6560 6005,6555 ; v3(6055,6605) 6005,6555
  Signal Layer 3 w10: v3(6055,6605) 6055,6940 J25.2@6110,6995
  Bottom Layer w9.8: v5(4915,6530) 4955,6530 5026.66,6458.34 5026.66,6458.05 5031.1,6453.61 U6.39@5031.1,6422.4
EN4: J26.2 U6.43 | length 1651.1
  Signal Layer 2 w10: v5(5060,6540) 5060,6595 5165,6700 6140,6700 6175,6735 v3(6175,6740)
  Signal Layer 3 w10: v3(6175,6740) 6175,6935 J26.2@6235,6995
  Bottom Layer w9.8: v5(5060,6540) 5095,6505 5095,6489.99 5097.35,6487.64 5097.35,6487.33 5109.84,6474.84 U6.43@5109.84,6422.4
FB: C13.1 C121.2 C196.1 CC.1 D3.2 D5.1 J2.11 J28.11 R44.2 R160.2 R161.2 R163.2 R168.2 U1.45 U6.45 | length 11651.6
  Top Layer w10: v3(2305,8315) R163.2@2305,8375 ; D3.2@3128.35,8205 3128.35,8181.65 3140,8170 3195,8170 3205,8160 D5.1@3205,8120 ; D5.1@3203.31,8125 3203.31,8091.69 3220,8075 ; v3(3220,8045) 3220,8075 ; C121.2@3290,8075 3220,8075 ; C121.2@3290,8076.5 3368.5,8076.5 CC.1@3400,8045 CC.1@3405,8040
  Signal Layer 2 w10: v3(2305,8315) 2305,8110 2370,8045 v3(3220,8045) 3430,8045 3550,7925 4205,7925 4250,7880 4250,7790 J2.11@4300,7740 ; v3(2495,6840) 2595,6840 2625,6810 2715,6810 2745,6840 3310,6840 v3(3330,6820) 3405,6745 v3(3620,6745) ; v3(4495,6840) 5310,6840 5330,6820 5350,6840 v5(5640,6840)
  Signal Layer 3 w9.8: v3(3140,6505) 3140,6580 3235,6675 v3(3285,6675) ; v5(5140,6505) 5140,6580 5235,6675 v3(5285,6675)
  Bottom Layer w9.8: C13.1@3135,6545 3140,6540 v3(3140,6505) 3140,6500 3149.21,6490.79 U1.45@3149.21,6422.4 ; v3(3285,6675) 3620,6675 ; J2.11@4300,7740 4340,7700 4340,7450 ; v3(5285,6675) 5330,6720 v3(5330,6825) 5330,7070 J28.11@5290,7110
  Bottom Layer w10: v3(2495,6840) 2485,6840 2455,6810 2455,6335 2540,6250 R161.2@2540,6206.5 R161.2@2540,6205 ; v3@3620,6740 3620,6675 3620,6230 3700,6150 R160.2@3700,6146.5 ; v3(3620,6745) 3635,6745 3730,6840 ; 4340,7450 3730,6840 ; v3@4500,6840 v3(4495,6840) v3@4485,6840 ; R44.2@4540,6206.5 4540,6250 4455,6335 4455,6810 v3@4485,6840 ; C196.1@5135,6550 C196.1@5135,6547.44 5135,6506.57 5134.21,6505.79 5149.21,6490.79 U6.45@5149.21,6422.4 ; v5@5640,6845 v5(5640,6840) 5699.93,6780.07 R168.2@5699.93,6146.5 ; 3730,6840 v3@4485,6840
HO1: R26.1 R30.1 U1.22 | length 2680.8
  Top Layer w24: v1(1890,4755) R30.1@1980,4755 ; v1@1895,4250 R26.1@1960,4250
  Signal Layer 2 w24: v1(1890,4250) v1(1890,4755) 1890,5215 2665,5990 v5(3010,5990)
  Bottom Layer w9.8: 3031.1,6034.07 U1.22@3031.1,6101.54
  Bottom Layer w16: v5(3010,5990) 3010,6005 3030,6025 3030,6034.07
HO2: R37.1 R41.1 U1.15 | length 4190.1
  Top Layer w24: v1(6310,5260) 6350,5220 R41.1@6350,5205 ; v1(6350,4775) 6350,4710 R37.1@6355,4705
  Signal Layer 2 w24: v5(3190,6000) 4170.08,6000 4538.2,5631.87 4538.2,5631.8 4910,5260 v1(6310,5260) 6350,5220 6350,4931.61 6350.87,4930.73 6350.87,4775.87 v1(6350,4775)
  Bottom Layer w9.8: 3168.9,6030 U1.15@3168.9,6101.54
  Bottom Layer w16: 3167.82,6036.25 3167.82,6031.08 3168.9,6030 3170,6030 3190,6010 v5(3190,6000)
HO3: R179.1 R183.1 U6.22 | length 10412.2
  Signal Layer 2 w12: v1@1840,2840 1845,2845 v1(1845,2850)
  Signal Layer 2 w24: v1(1845,2350) v1@1845,2845 ; v1(1845,2850) 1845,2850.08 2654.92,3660 6798.13,3660 6833.13,3695 6833.13,5271.87 6535,5570 4900,5570 4780,5690 4780,5924.27 4779.13,5925.14 4779.13,5954.86 4814.27,5990 v5(5010,5990)
  Bottom Layer w9.8: U6.22@5031.1,6097.6 5031.1,6058.29 5033.28,6056.11 5033.28,6033.28
  Bottom Layer w16: v5(5010,5990) 5010,6010 5033.28,6033.28
  Bottom Layer w24: R179.1@1845,2280 v1(1845,2350) ; R183.1@1845,2785 v1(1845,2850)
HO4: R190.1 R194.1 U6.15 | length 6996.8
  Signal Layer 2 w24: v5(5190,6000) 6820,6000 7230,5590 7230,2924.92 7208.2,2903.13 7208.13,2903.13 7160,2855 6400,2855 6365,2820 v1(6365,2365) v1(6365,1855)
  Bottom Layer w9.8: 5168.9,6021.1 U6.15@5168.9,6097.6
  Bottom Layer w16: 5168.9,6021.1 v5(5190,6000)
  Bottom Layer w24: R190.1@6365,1785 v1(6365,1855) ; v1(6365,2365) 6365,2300 R194.1@6370,2295
I2C_SCL: R152.1 U23.112 U28.6 | length 347.1
  Bottom Layer w6: U23.112@4188.15,8327.87 4247.13,8327.87 4265,8310
  Bottom Layer w8: 4265,8310 4295,8310 ; 4296.38,8311.94 4310.4,8311.94 4310.47,8311.87 4324.53,8311.87 4324.6,8311.94 4343.62,8311.94 4344.51,8312.84 4345.47,8311.87 4356.87,8311.87 R152.1@4385,8340 ; U28.6@4365,8220 4365,8295 4385,8315 R152.1@4385,8340 ; R152.1@4385,8343.5 R152.1@4385,8340
I2C_SDA: R151.1 U23.111 U28.5 | length 351.4
  Signal Layer 3 w8: v3(4275,8380) 4335,8320 v3(4335,8285)
  Bottom Layer w6: U23.111@4188.15,8343.62 4218.62,8343.62 4255,8380 v3(4275,8380)
  Bottom Layer w8: v3(4275,8380) 4311.5,8343.5 R151.1@4320,8343.5 ; R151.1@4319.25,8344.25 R151.1@4320,8345 ; v3(4335,8285) 4340,8285 4341.61,8283.39 U28.5@4341.61,8222.2
I_TOTAL: R16.1 R21.2 R32.1 R173.2 R184.1
  other v3: 3600,2385 3650,2385 3700,2385 3750,2385 3800,2385 3850,2385 4425,2385 4475,2385 4525,2385 3600,2435 3650,2435 3700,2435 3750,2435 3800,2435 3850,2435 4425,2435 4475,2435 4525,2435 3600,2485 3650,2485 3700,2485 3750,2485 3800,2485 3850,2485 4425,2485 4475,2485 4525,2485 3600,2535 3650,2535 3700,2535 3750,2535 3800,2535 3850,2535 4425,2535 4475,2535 4525,2535 3600,2585 3650,2585 3700,2585 3750,2585 3800,2585 3850,2585 4425,2585 4475,2585 4525,2585 3600,2635 3650,2635 3700,2635 3750,2635 3800,2635 3850,2635 3600,2685 3650,2685 3700,2685 3750,2685 3800,2685 3850,2685 4425,2685 4475,2685 4525,2685 3600,2735 3650,2735 3700,2735 3750,2735 3800,2735 3850,2735 4425,2735 4475,2735 4525,2735 3600,4800 3650,4800 3700,4800 3750,4800 3800,4800 3850,4800 4425,4800 4475,4800 4525,4800 3600,4850 3650,4850 3700,4850 3750,4850 3800,4850 3850,4850 4425,4850 4475,4850 4525,4850 3600,4900 3650,4900 3700,4900 3750,4900 3800,4900 3850,4900 4425,4900 4475,4900 4525,4900 3600,4950 3650,4950 3700,4950 3750,4950 3800,4950 3850,4950 4425,4950 4475,4950 4525,4950 3600,5000 3650,5000 3700,5000 3750,5000 3800,5000 3850,5000 4425,5000 4475,5000 4525,5000 3600,5050 3650,5050 3700,5050 3750,5050 3800,5050 3850,5050 3600,5100 3650,5100 3700,5100 3750,5100 3800,5100 3850,5100 4425,5100 4475,5100 4525,5100 3600,5150 3650,5150 3700,5150 3750,5150 3800,5150 3850,5150 4425,5150 4475,5150 4525,5150 3600,5200 3650,5200 3700,5200 3750,5200 3800,5200 3850,5200 4425,5200 4475,5200 4525,5200
  other v9: 4425,2635 4475,2635 4525,2635 4425,5050 4475,5050 4525,5050
IBAT: C113.2 R73.1 R114.1 | length 1111.1
  Top Layer w12: C113.2@2840,8620 2836.5,8623.5 R73.1@2836.5,8710 v7(2890,8710) ; v5(3735,8695) 3747.01,8695 3748.5,8693.5 R114.1@3795,8693.5
  Signal Layer 2 w12: v7(2890,8710) 2960,8640 3695,8640 3735,8680 v5(3735,8695)
IBAT_P: C110.1 R71.1 R74.1 U14.3 | length 801.1
  Top Layer w12: C110.1@2755,8220 2751.5,8216.5 R71.1@2680,8216.5 U14.3@2680,8346.65 2680,8415 2720,8455 2860,8455 2890,8485 2890,8660 2935,8705 R74.1@2983.5,8705
IOUT1: C2.2 J2.5 R3.1 U1.37 | length 2459.9
  Signal Layer 3 w8: v7(2850,6710) 2850,6875 2935,6960 3165,6960 3245,6880 3310,6880 3860,7430 3860,7510 4000,7650 J2.5@4000,7740
  Bottom Layer w8: C2.2@2710,6735 2830,6735 2850,6715 v7(2850,6710) 2850,6500 2870,6480 2967.65,6480 2991.73,6455.92 U1.37@2991.73,6418.46
  Bottom Layer w9.8: R3.1@2650,6732.56 C2.2@2710,6732.56
IOUT2: C17.1 J2.9 R20.2 U1.38 | length 2350
  Signal Layer 3 w10: v3(2890,6505) 2890,6725 2980,6815 v7(3015,6815)
  Bottom Layer w8: v3(2890,6505) 2965.1,6505 3011.42,6458.68 U1.38@3011.42,6418.46
  Bottom Layer w10: v7(3015,6815) 3094.92,6735.08 C17.1@3192.48,6735.08 ; C17.1@3190,6737.55 C17.1@3192.48,6735.08 ; 4200,7465 4200,7460 ; J2.9@4200,7720 4200,7460 ; C17.1@3192.48,6735.08 R20.2@3240,6735.08 3475.08,6735.08 4200,7460
IOUT3: C9.2 J28.5 R9.1 U6.37 | length 1059.4
  Signal Layer 3 w8: v5(4850,6710) 4850,6880 4990,7020 J28.5@4990,7110
  Bottom Layer w9.8: v5(4850,6710) 4850,6500 4885,6465 4965,6465 4991.73,6438.27 U6.37@4991.73,6422.4
  Bottom Layer w10: R9.1@4650,6730 4830,6730 v5(4850,6710)
IOUT4: C205.1 J28.9 R171.2 U6.38 | length 1187.3
  Signal Layer 3 w10: v5(4890,6505) 4890,6725 4980,6815 v5(5015,6815)
  Bottom Layer w9.8: v5(4890,6505) 4955.01,6505 5008.98,6451.02 5008.98,6450.73 5011.42,6448.3 U6.38@5011.42,6422.4
  Bottom Layer w10: v5(5015,6815) 5094.92,6735.08 C205.1@5192.48,6735.08 ; J28.9@5190,7110 5192.48,7107.52 C205.1@5192.48,6735.08 ; R171.2@5240,6735 5239.92,6735.08 C205.1@5192.48,6735.08
IREF: J18.2 J18.4 R93.1 | length 1447.5
  Top Layer w10: R93.1@3270,8735 3295,8710 v5(3310,8710)
  Signal Layer 5 w10: J18.4@2550,9320 2600,9370 2685,9370 2700,9355 2700,8940 2730,8910 3110,8910 v5(3310,8710)
  Bottom Layer w10: J18.2@2450,9320 J18.4@2550,9320
ISEN+: R31.1 R63.1 R195.2 | length 1283.5
  Top Layer w10: R63.1@2540,6735 2455,6820 2455,6930 2685,7160 2750,7160 2935,7345 2935,7460 2909.87,7485.13 2909.87,7485.3 2895.3,7499.87 2895.13,7499.87 2890,7505 2880,7505 2855,7530 ; R31.1@2542.44,6682.44 R63.1@2542.44,6730 ; 2855,7540 2855,7530 ; R195.2@2898.5,7615 2870,7615 2855,7600 2855,7530
ISEN-: R42.1 R64.1 R65.2 | length 1496.7
  Top Layer w10: R42.1@2542.44,6905 2542.44,6952.16 2714.53,7124.25 2799.25,7124.25 3035,7360 3435,7360 3550,7475 R64.1@3550,7590 ; R65.2@3456.5,7630 3510,7630 3515,7630 R64.1@3550,7595 ; R64.1@3552.44,7595 R64.1@3552.44,7597.44
JTAG_RESET: J22.1 R141.1 S2.2 | length 3390.1
  Top Layer w8: v3(3390,8770) 3400,8780 S2.2@3475,8780 ; v3(3795,8400) R141.1@3795,8463.5
  Signal Layer 5 w8: v3(3795,8400) 3770,8375 3625,8375 3600,8400 3600,8420 3390,8630 v3(3390,8770) 3390,8810 3785,9205 5369.39,9205 5428.74,9264.35 5499.35,9264.35 J22.1@5660,9425
LDACn: J17.7 R99.2 U17.1 | length 732.1
  Top Layer w8: U17.1@3174.06,9039.13 3254.92,9120 v7(3485,9120)
  Bottom Layer w8: v7(3485,9120) 3515,9150 3515,9325 J17.7@3565,9375 3530,9410 R99.2@3530,9460
LO1: R27.1 R28.1 U1.20 | length 3427.5
  Top Layer w24: R27.1@2090,3945 R27.1@2090,3950 v1(2090,4015) ; R28.1@2595,3945 R28.1@2595,3950 v1(2595,4015)
  Signal Layer 2 w24: v1(2090,4015) v1(2595,4015) 3065,4015 3330,4280 3330,5225 3085,5470 3085,5845 3078.13,5851.87 3078.13,6011.87 3060,6030 v5(3060,6050)
  Bottom Layer w9.8: 3070.47,6060.47 U1.20@3070.47,6101.54
  Bottom Layer w12: v5(3060,6050) 3070.47,6060.47
LO2: R38.1 R39.1 U1.17 | length 4223.8
  Top Layer w24: R39.1@5210,3950 v1(5210,4015) ; R38.1@5705,3950 v1(5705,4015)
  Signal Layer 2 w24: v5@3141.87,6048.13 3150,6040 3150,5930 3190,5890 4105,5890 4460,5535 4460.08,5535 4861.87,5133.2 4861.87,4163.13 5010,4015 v1(5210,4015) v1(5705,4015)
  Bottom Layer w9.8: 3129.53,6060.47 U1.17@3129.53,6101.54
  Bottom Layer w12: 3129.53,6060.47 v5(3140,6050)
LO3: R180.1 R181.1 U6.20 | length 10167.1
  Signal Layer 2 w24: v1(2510,1630) v1(3015,1630) 3040.29,1655.29 3040.29,1743.69 3040.15,1743.83 3040.15,1770.23 3040.29,1770.37 3040.29,1775.29 3057.31,1792.31 3057.31,1792.76 3137.04,1872.5 ; 3137.5,1872.5 3330,2065 3330,2815 3866.87,3351.87 4686.8,3351.87 4859.92,3525 6865,3525 6950,3610 6950,5380 6631.87,5698.13 5056.8,5698.13 4978.13,5776.8 4978.13,5848.2 5060,5930.08 v5(5060,6050)
  Bottom Layer w9.8: v5(5060,6050) 5070.47,6060.47 U6.20@5070.47,6097.6
  Bottom Layer w24: R180.1@2510,1565 v1(2510,1630) ; R181.1@3010,1565 3015,1570 v1(3015,1630)
LO4: R191.1 R192.1 U6.17 | length 9444
  Signal Layer 2 w24: v5(5140,6050) 5141.87,6048.13 5141.87,5914.66 5189.66,5866.87 6823.13,5866.87 7115,5575 7115,3560 7111.87,3556.87 7111.87,3556.8 6953.2,3398.13 5123.13,3398.13 4835,3110 4835,2025 5073.13,1786.87 5283.13,1786.87 5440,1630 v1(5625,1630) ; v1@5630,1630 v1(6120,1630)
  Bottom Layer w9.8: U6.17@5129.53,6097.6 5129.53,6060.47 v5(5140,6050)
  Bottom Layer w24: R192.1@5625,1565 v1(5625,1630) ; v1(6120,1630) 6120,1570 R191.1@6125,1565
NetC1_1: C1.1 R1.2 U1.28 | length 287
  Top Layer w8: v5(2815,6170) 2860,6215 C1.1@2897.44,6215
  Bottom Layer w8: R1.2@2772.56,6170 v5(2815,6170) 2855.79,6210.79 U1.28@2941.54,6210.79
NetC3_2: C3.2 C4.2 R161.1 U1.26 | length 612.9
  Signal Layer 2 w8: v3(2540,6090) 2555,6075 2800,6075 v3(2830,6105)
  Bottom Layer w8: v3(2540,6090) R161.1@2540,6143.5 ; C4.2@2775,6120 2800,6120 2815,6105 v3(2830,6105) 2896.42,6171.42 U1.26@2941.54,6171.42
  Bottom Layer w9.8: C3.2@2716.9,6120 C3.2@2717.56,6120 ; C3.2@2725.12,6122.56 C4.2@2775,6122.56
NetC4_1: C4.1 R2.1 | length 49.9
  Bottom Layer w9.8: R2.1@2722.56,6070 C4.1@2772.44,6070
NetC5_1: C5.1 R5.2 U1.8 | length 348.7
  Top Layer w8: C5.1@3302.56,6200 3312.56,6210 3325,6210 v5(3380,6265)
  Bottom Layer w8: U1.8@3258.46,6230.47 3345.47,6230.47 v5(3380,6265) 3405,6265 3437.56,6297.56 R5.2@3437.56,6335
NetC7_2: C7.2 R54.1 U1.23 | length 188.2
  Bottom Layer w9.8: 3011.42,6046.42 U1.23@3011.42,6101.54
  Bottom Layer w12: 3005,6040 3011.42,6046.42
  Bottom Layer w16: R54.1@2955,5935 C7.2@2955,5992.44 ; C7.2@2955,6000 2965,6000 3005,6040
NetC8_1: C8.1 R8.2 U6.28 | length 296.1
  Top Layer w10: v5(4815,6170) 4860,6215 C8.1@4902.44,6215 C8.1@4905,6215
  Bottom Layer w9.8: R8.2@4770,6170 R8.2@4772.56,6170 v5(4815,6170) 4815,6175 4850.79,6210.79 U6.28@4937.6,6210.79
NetC12_1: C12.1 R55.1 U1.14 | length 242.9
  Bottom Layer w9.8: 3188.58,6046.42 U1.14@3188.58,6101.54
  Bottom Layer w12: 3188.58,6046.42 3195,6040 ; 3220,6015 3221.15,6015 3222.44,6015
  Bottom Layer w16: 3195,6040 3221.15,6015 C12.1@3245,5992.44 3277.56,5992.44 3295,5975 R55.1@3295,5925
NetC14_1: C14.1 U1.12 | length 241.7
  Bottom Layer w8: U1.12@3258.46,6151.73 3258.46,6131.54 3370,6020 C14.1@3427.44,6020 ; C14.1@3424.44,6025 C14.1@3428.94,6029.5
NetC15_1: C15.1 C16.1 R160.1 U1.11 | length 654.4
  Signal Layer 3 w8: v3(3350,6115) 3425,6040 v3(3640,6040)
  Bottom Layer w8: U1.11@3258.46,6171.42 3259.88,6170 3295,6170 v3(3350,6115) 3387.56,6077.44 C15.1@3430,6077.44 C16.1@3474.88,6077.44 ; v3(3640,6040) 3656.5,6040 R160.1@3700,6083.5
NetC15_2: C15.2 R19.2 | length 44.9
  Bottom Layer w8: C15.2@3432.56,6130 R19.2@3477.44,6130
NetC19_2: C19.2 C30.2 R44.1 U6.26 | length 621.3
  Signal Layer 2 w8: v5(4540,6090) 4555,6075 4800,6075 v5(4830,6105)
  Bottom Layer w8: v5(4540,6090) R44.1@4540,6143.5
  Bottom Layer w10: C19.2@4715,6120 C19.2@4722.56,6120 4815,6120 v5(4830,6105) 4875.85,6150.85 4875.85,6155.68 4891.59,6171.42 U6.26@4937.6,6171.42
NetC30_1: C30.1 R23.1 | length 47.4
  Bottom Layer w10: R23.1@4722.56,6070 C30.1@4770,6070
NetC31_1: C31.1 R43.2 U6.8 | length 353.7
  Top Layer w9.8: C31.1@5297.56,6200 5320,6200 5380,6260 v5(5380,6265)
  Bottom Layer w9.8: U6.8@5262.4,6230.47 5263.41,6231.48 5288.84,6231.48 5297.36,6240 5355,6240 v5(5380,6265) 5400,6265 5435,6300 R43.2@5435,6340
NetC35_1: C35.1 R164.1 U3.5 | length 171.9
  Top Layer w16: R164.1@5505,8840 C35.1@5590,8840 5592.6,8842.6 U3.5@5675.87,8842.6
NetC37_1: C37.1 R165.1 U4.5 | length 176.9
  Top Layer w16: R165.1@5505,8600 C37.1@5585,8600 ; C37.1@5590,8600 C37.1@5585,8600 ; U4.5@5675.87,8602.6 5587.6,8602.6 C37.1@5585,8600
NetC41_1: C41.1 D7.1 L3.1 Q14.1 Q14.2 Q14.3 U5.20 | length 674.1
  Top Layer w13: U5.20@6410.16,8762.8 6410.16,8724.84 6432.56,8702.44 C41.1@6432.56,8650 v5(6480,8650) v5@6485,8650
  Signal Layer 3 w13: v5@6480,8645 v5@6485,8650
  Signal Layer 3 w16: v5@6480,8645 6800,8325 v7(6840,8325)
NetC41_2: C41.2 U5.18 | length 120.4
  Top Layer w13: U5.18@6358.98,8762.8 6358.98,8716.02 6370,8705 6370,8657.44 C41.2@6377.44,8650
NetC42_1: C42.1 C43.1 D6.1 J4.1 R51.2 U5.10 | length 1656.9
  Top Layer w10: v5(5955,8550) 6052.56,8647.56 R51.2@6052.56,8965 6110,8965 6115.13,8970.13 6115.13,8970.3 6129.7,8984.87 6129.87,8984.87 6132.2,8987.2 U5.10@6179.84,8987.2
  Signal Layer 3 w10: J4.1@5750,7570 5750,8060 5955,8265 v5(5955,8550)
NetC44_1: C44.1 U5.7 | length 166.3
  Top Layer w10: C44.1@6235.31,9144.64 6235.31,9104.69 6256.61,9083.39 U5.7@6256.61,8987.2
NetC45_1: C45.1 U5.5 | length 160.6
  Top Layer w10: U5.5@6307.8,8987.2 6307.8,9072.8 6315.31,9080.31 C45.1@6315.31,9144.64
